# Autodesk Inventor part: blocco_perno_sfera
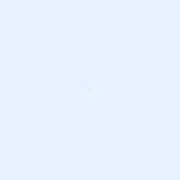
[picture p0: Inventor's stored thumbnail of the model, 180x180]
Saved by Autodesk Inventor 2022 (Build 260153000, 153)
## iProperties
Created: 2021-12
Part Number: blocco_perno_sfera
Material: Generico
Document SubType Name: Modeling
Designer: admin
Density: 1 g/cm^3
Appearance: Default
Author: admin
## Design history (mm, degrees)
sketch "Schizzo1"
  geometry: 1 further point
  constraints: 1 other
